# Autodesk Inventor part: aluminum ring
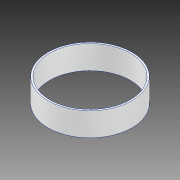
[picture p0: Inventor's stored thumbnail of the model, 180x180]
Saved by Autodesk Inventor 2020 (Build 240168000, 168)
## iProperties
Created: 2019-12
Part Number: aluminum ring
Material: Aluminum 6061
Document SubType Name: Modeling
Designer: MPI
Density: 2.7 g/cm^3
Appearance: Aluminum - Flat
Author: MPI
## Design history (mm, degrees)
sketch "Sketch1"
  geometry: C1 r 76.302 at (0, 0); C2 r 79.375 at (0, 0); 1 further point
  constraints: 2 centre point, 2 coincident
  dimensions: "d0" = 152.6032 diameter of C1; "d1" = 158.75 diameter of C2
extrude "Extrusion1" new body sketch "Sketch1" distance "d2" = 44.45; taper "d3" = 0 deg
body "Solid1"
